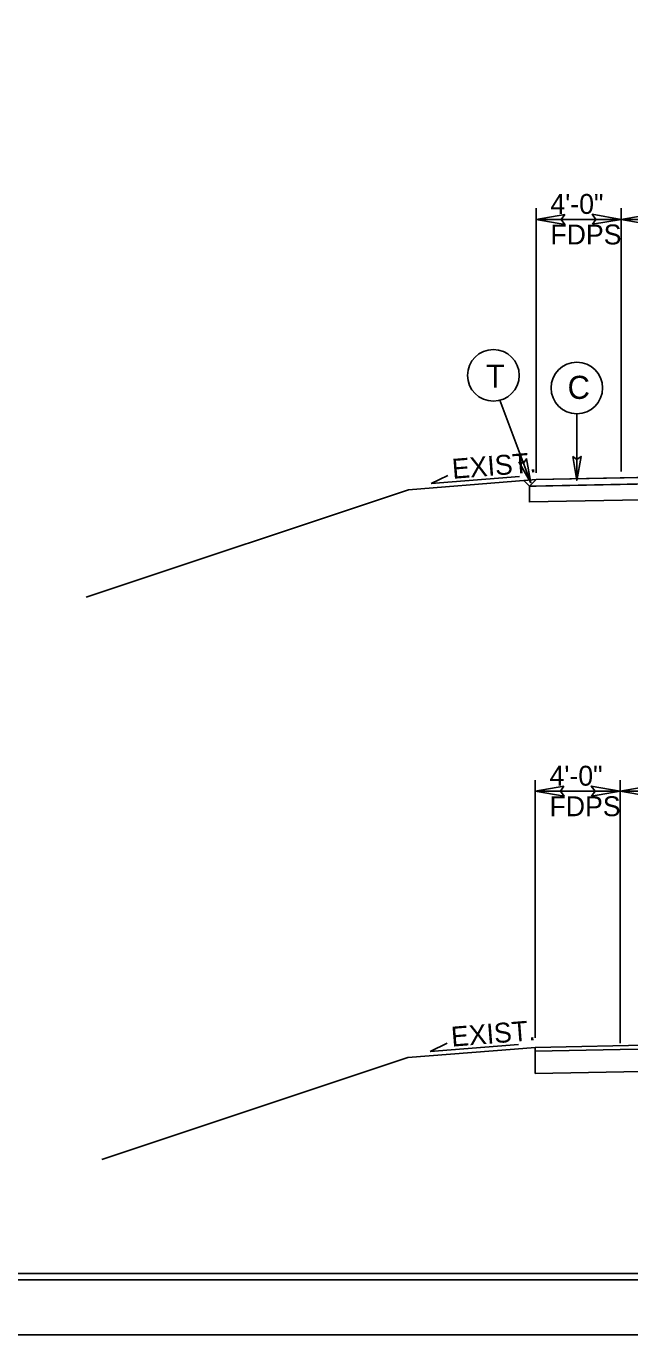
# Model space of a CAD drawing. Extents: x 2137858 to 2138172, y 2136084 to 2136289.
# Drawn here: x 2137934.9 to 2137980.7, y 2136083.7 to 2136183.1 of the extents above; entities that cross this region are included whole.
import ezdxf

# ---------------------------------------------------------------- set-up
doc = ezdxf.new("R2010")
doc.units = 0
for name, color, linetype in [('Old_Level_1', 7, 'Continuous'), ('Old_Level_11', 7, 'Continuous'), ('Old_Level_2', 7, 'Continuous'), ('Old_Level_20', 7, 'Continuous'), ('Sheet Cutting Line CELL', 7, 'Continuous'), ('Sheet Plot Border Inside CELL', 7, 'Continuous'), ('Sheet Plot Border Outside CELL', 7, 'Continuous'), ('Sheet Typical CELL', 7, 'Continuous')]:
    doc.layers.add(name, color=color, linetype=linetype)

msp = doc.modelspace()

# ---------------------------------------------------------------- linework, layer by layer
at = {"layer": 'Old_Level_1'}
for p, q in [((2137965.658, 2136148.348), (2137966.935, 2136148.969)), ((2137972.365, 2136148.883), (2137965.658, 2136148.348)), ((2138004.245, 2136148.772), (2137973.125, 2136148.15)), ((2137963.949, 2136147.88), (2137939.463, 2136139.718)), ((2137972.058, 2136148.529), (2137963.949, 2136147.88)), ((2137973.629, 2136148.654), (2137972.058, 2136148.529)), ((2137973.125, 2136148.15), (2137973.125, 2136146.948)), ((2138004.236, 2136147.57), (2137973.125, 2136146.95)), ((2138010.907, 2136106.254), (2137973.562, 2136105.509)), ((2137971.991, 2136105.383), (2137963.882, 2136104.734)), ((2137965.591, 2136105.202), (2137966.868, 2136105.823)), ((2137972.298, 2136105.738), (2137965.591, 2136105.202)), ((2137973.562, 2136105.509), (2137971.991, 2136105.383)), ((2137973.562, 2136105.509), (2137973.562, 2136103.516)), ((2137980.015, 2136105.341), (2137973.562, 2136105.212)), ((2138010.907, 2136105.958), (2137980.015, 2136105.341)), ((2137963.882, 2136104.734), (2137940.662, 2136096.995)), ((2138004.169, 2136104.128), (2137973.562, 2136103.518))]:
    msp.add_line(p, q, dxfattribs=at)
msp.add_lwpolyline([(2138004.236, 2136149.266), (2138034.889, 2136149.88), (2138035.374, 2136149.395), (2138004.245, 2136148.772), (2137973.629, 2136148.16), (2137973.125, 2136148.15), (2137973.629, 2136148.655)], close=True, dxfattribs=at)
at = {"layer": 'Old_Level_11'}
for p, q in [((2137973.629, 2136169.263), (2137973.629, 2136149.172)), ((2137980.082, 2136169.263), (2137980.082, 2136149.267)), ((2137980.082, 2136168.422), (2137973.629, 2136168.422)), ((2138004.236, 2136168.422), (2137980.082, 2136168.422)), ((2137980.082, 2136164.278), (2137980.082, 2136149.609)), ((2137970.879, 2136154.699), (2137973.241, 2136148.411)), ((2137976.724, 2136153.653), (2137976.724, 2136148.587)), ((2137973.562, 2136125.82), (2137973.562, 2136106.25)), ((2137980.015, 2136124.98), (2137973.562, 2136124.98)), ((2137980.015, 2136125.82), (2137980.015, 2136105.825)), ((2138004.169, 2136124.98), (2137980.015, 2136124.98)), ((2137980.015, 2136120.836), (2137980.015, 2136106.166))]:
    msp.add_line(p, q, dxfattribs=at)
for points in [[(2137975.807, 2136168.796), (2137973.629, 2136168.422), (2137975.82, 2136168.035), (2137975.541, 2136168.422)], [(2137977.904, 2136168.048), (2137980.082, 2136168.422), (2137977.891, 2136168.809), (2137978.171, 2136168.422)], [(2137982.26, 2136168.796), (2137980.082, 2136168.422), (2137982.273, 2136168.035), (2137981.994, 2136168.422)], [(2137972.312, 2136150.002), (2137973.241, 2136148.411), (2137972.904, 2136150.233), (2137972.683, 2136149.904)], [(2137976.411, 2136150.402), (2137976.724, 2136148.587), (2137977.047, 2136150.412), (2137976.724, 2136150.181)], [(2137975.74, 2136125.354), (2137973.562, 2136124.98), (2137975.753, 2136124.592), (2137975.474, 2136124.98)], [(2137977.837, 2136124.605), (2137980.015, 2136124.98), (2137977.825, 2136125.367), (2137978.104, 2136124.98)], [(2137982.193, 2136125.354), (2137980.015, 2136124.98), (2137982.206, 2136124.592), (2137981.927, 2136124.98)]]:
    msp.add_lwpolyline(points, close=True, dxfattribs=at)
for centre in [(2137970.388, 2136156.57), (2137976.725, 2136155.615)]:
    msp.add_circle(centre, 1.96, dxfattribs=at)
at = {"layer": 'Old_Level_2'}
for p, q in [((2138004.236, 2136149.266), (2137973.629, 2136148.655)), ((2137980.082, 2136148.783), (2137973.629, 2136148.654)), ((2137972.696, 2136148.579), (2137973.125, 2136148.15)), ((2137973.629, 2136148.655), (2137973.125, 2136148.15))]:
    msp.add_line(p, q, dxfattribs=at)
at = {"layer": 'Sheet Cutting Line CELL'}
msp.add_line((2137858.136, 2136083.673), (2138172.482, 2136083.673), dxfattribs=at)
at = {"layer": 'Sheet Plot Border Inside CELL'}
msp.add_lwpolyline([(2138171.642, 2136284.815), (2137860.562, 2136284.815), (2137860.562, 2136087.863), (2138171.642, 2136087.863)], close=True, dxfattribs=at)
at = {"layer": 'Sheet Plot Border Outside CELL'}
msp.add_lwpolyline([(2138172.482, 2136289.006), (2137858.136, 2136289.006), (2137858.136, 2136083.673), (2138172.482, 2136083.673)], close=True, dxfattribs=at)
at = {"layer": 'Sheet Typical CELL'}
msp.add_lwpolyline([(2138169.309, 2136284.339), (2137889.309, 2136284.339), (2137889.309, 2136088.339), (2138169.309, 2136088.339)], close=True, dxfattribs=at)

# ---------------------------------------------------------------- texts
at = {"layer": 'Old_Level_1'}
for s, p in [('4\'-0"', (2137974.718, 2136168.839)), ('FDPS', (2137974.718, 2136166.52)), ('4\'-0"', (2137974.651, 2136125.397)), ('FDPS', (2137974.651, 2136123.078))]:
    msp.add_text(s, height=1.5125, dxfattribs=at).set_placement(p)
for p in [(2137967.306, 2136148.708), (2137967.239, 2136105.563)]:
    msp.add_text('EXIST.', height=1.5125, rotation=4.57168, dxfattribs=at).set_placement(p)
at = {"layer": 'Old_Level_20'}
for s, p in [('T', (2137969.818, 2136155.641)), ('C', (2137976.022, 2136154.784))]:
    msp.add_text(s, height=1.754, dxfattribs=at).set_placement(p)

doc.saveas('drawing.dxf')
